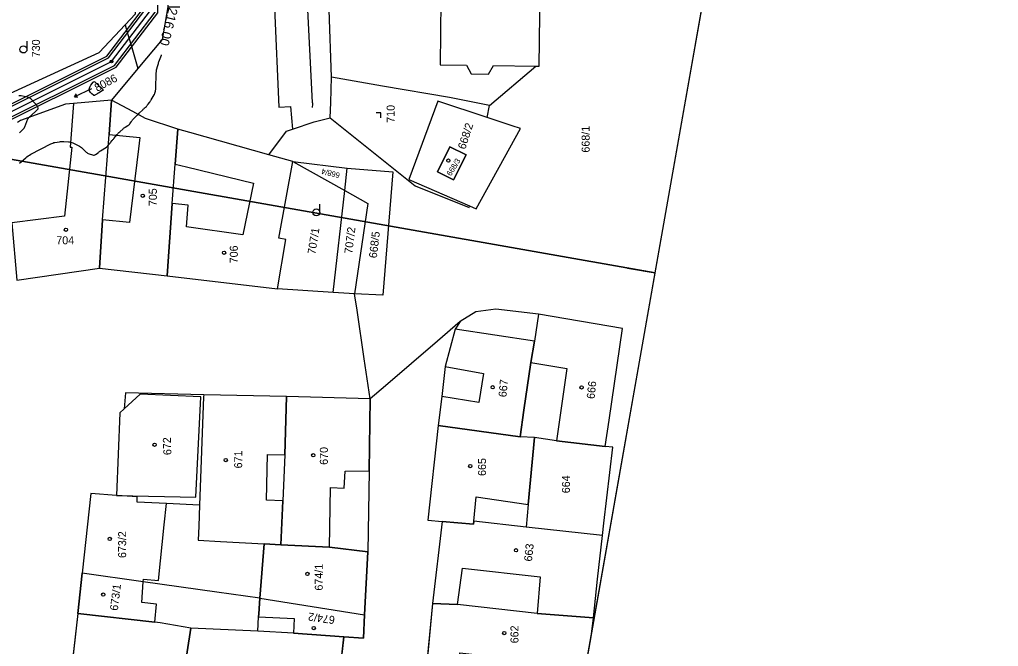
# Model space of a CAD drawing. Extents: x -534481 to -534256, y -1190577 to -1190138.
# Drawn here: x -534365.7 to -534261.7, y -1190410 to -1190343.4 of the extents above; entities that cross this region are included whole.
import ezdxf

# ---------------------------------------------------------------- set-up
doc = ezdxf.new("R2010")
doc.units = 0
for name, color, linetype in [('0_kroužky', 7, 'Continuous'), ('30', 7, 'Continuous'), ('31', 7, 'Continuous'), ('40', 7, 'Continuous'), ('_N_osa', 7, 'Continuous'), ('_N_tenká', 7, 'Continuous'), ('_rámeček', 7, 'Continuous'), ('_rámeček_mřížka', 7, 'Continuous'), ('Hranice parcel', 7, 'Continuous'), ('Parcelní čísla', 7, 'Continuous'), ('Polygon budovy', 7, 'Continuous'), ('Značky budov', 7, 'Continuous'), ('Značky kultur', 7, 'Continuous')]:
    doc.layers.add(name, color=color, linetype=linetype)

msp = doc.modelspace()

# ---------------------------------------------------------------- linework, layer by layer
at = {"layer": '0_kroužky'}
msp.add_circle((-534355.89, -1190347.82), 0.15, dxfattribs=at)
msp.add_circle((-534355.89, -1190347.82), 0.15, dxfattribs=at)
msp.add_circle((-534355.89, -1190347.82), 0.15, dxfattribs=at)
msp.add_circle((-534355.89, -1190347.82), 0.15, dxfattribs=at)
msp.add_circle((-534355.89, -1190347.82), 0.15, dxfattribs=at)
msp.add_circle((-534355.89, -1190347.82), 0.15, dxfattribs=at)
at = {"layer": '30'}
msp.add_lwpolyline([(-534365.67, -1190358.61), (-534365.01, -1190358.03), (-534364.89, -1190357.93), (-534364.76, -1190357.83), (-534364.62, -1190357.75), (-534364.48, -1190357.67), (-534362.35, -1190356.56), (-534362.24, -1190356.51), (-534362.13, -1190356.47), (-534362.02, -1190356.43), (-534361.9, -1190356.41), (-534361.42, -1190356.33), (-534361.3, -1190356.31), (-534361.18, -1190356.3), (-534361.07, -1190356.3), (-534360.95, -1190356.31), (-534360.47, -1190356.34), (-534360.35, -1190356.36), (-534360.23, -1190356.38), (-534360.12, -1190356.42), (-534360.01, -1190356.46), (-534359.42, -1190356.74), (-534359.31, -1190356.79), (-534359.2, -1190356.86), (-534359.1, -1190356.94), (-534359, -1190357.02), (-534358.59, -1190357.43), (-534358.52, -1190357.49), (-534358.44, -1190357.54), (-534358.36, -1190357.58), (-534358.28, -1190357.61), (-534357.9, -1190357.73), (-534357.82, -1190357.75), (-534357.75, -1190357.75), (-534357.68, -1190357.73), (-534357.6, -1190357.69), (-534357.33, -1190357.5), (-534357.26, -1190357.45), (-534357.19, -1190357.4), (-534357.12, -1190357.35), (-534357.05, -1190357.31), (-534356.43, -1190356.9), (-534356.39, -1190356.87), (-534356.35, -1190356.84), (-534356.31, -1190356.8), (-534356.27, -1190356.76), (-534356.14, -1190356.6), (-534356.1, -1190356.56), (-534356.07, -1190356.52), (-534356.04, -1190356.47), (-534356.01, -1190356.43), (-534355.83, -1190356.21), (-534355.78, -1190356.16), (-534355.74, -1190356.1), (-534355.7, -1190356.05), (-534355.66, -1190356), (-534355.31, -1190355.57), (-534355.24, -1190355.49), (-534355.17, -1190355.42), (-534355.1, -1190355.34), (-534355.02, -1190355.27), (-534354.67, -1190354.95), (-534354.62, -1190354.9), (-534354.56, -1190354.85), (-534354.49, -1190354.81), (-534354.43, -1190354.77), (-534354.15, -1190354.62), (-534354.09, -1190354.58), (-534354.04, -1190354.54), (-534354, -1190354.5), (-534353.96, -1190354.45), (-534353.82, -1190354.23), (-534353.78, -1190354.17), (-534353.74, -1190354.12), (-534353.7, -1190354.07), (-534353.65, -1190354.02), (-534353.28, -1190353.63), (-534353.2, -1190353.55), (-534353.12, -1190353.47), (-534353.04, -1190353.39), (-534352.96, -1190353.31), (-534352.57, -1190352.93), (-534352.52, -1190352.89), (-534352.47, -1190352.84), (-534352.43, -1190352.8), (-534352.38, -1190352.75), (-534352.19, -1190352.58), (-534352.15, -1190352.53), (-534352.11, -1190352.48), (-534352.06, -1190352.43), (-534352.02, -1190352.38), (-534351.83, -1190352.13), (-534351.79, -1190352.07), (-534351.75, -1190352), (-534351.71, -1190351.94), (-534351.67, -1190351.88), (-534351.37, -1190351.37), (-534351.34, -1190351.32), (-534351.32, -1190351.27), (-534351.3, -1190351.22), (-534351.29, -1190351.17), (-534351.23, -1190350.95), (-534351.22, -1190350.9), (-534351.21, -1190350.84), (-534351.2, -1190350.79), (-534351.2, -1190350.73), (-534351.19, -1190350.43), (-534351.19, -1190350.36), (-534351.19, -1190350.29), (-534351.19, -1190350.22), (-534351.18, -1190350.15), (-534351.15, -1190349.59), (-534351.15, -1190349.51), (-534351.15, -1190349.44), (-534351.15, -1190349.37), (-534351.14, -1190349.29), (-534351.14, -1190348.99), (-534351.13, -1190348.92), (-534351.12, -1190348.85), (-534351.11, -1190348.77), (-534351.1, -1190348.7), (-534350.98, -1190348.23), (-534350.95, -1190348.13), (-534350.92, -1190348.03), (-534350.89, -1190347.93), (-534350.85, -1190347.83), (-534350.6, -1190347.14), (-534350.59, -1190347.09)], dxfattribs=at)
at = {"layer": '31'}
for points in [[(-534334.53, -1190352.7), (-534334.5, -1190352.33), (-534334.5, -1190352.32), (-534334.5, -1190352.32), (-534334.5, -1190352.31), (-534334.5, -1190352.31), (-534334.5, -1190352.31), (-534334.5, -1190352.3), (-534334.5, -1190352.29), (-534334.52, -1190352.22), (-534334.52, -1190352.19), (-534334.53, -1190352.19), (-534334.53, -1190352.18), (-534334.53, -1190352.18), (-534334.53, -1190352.17), (-534335.72, -1190328.89)], [(-534365.67, -1190355.38), (-534365.51, -1190355.23), (-534365.47, -1190355.19), (-534365.43, -1190355.15), (-534365.4, -1190355.12), (-534365.36, -1190355.08), (-534365.22, -1190354.92), (-534365.18, -1190354.88), (-534365.15, -1190354.84), (-534365.13, -1190354.79), (-534365.1, -1190354.75), (-534364.77, -1190353.91), (-534364.76, -1190353.88), (-534364.75, -1190353.86), (-534364.73, -1190353.83), (-534364.71, -1190353.81), (-534364.63, -1190353.73), (-534364.61, -1190353.71), (-534364.59, -1190353.69), (-534364.57, -1190353.67), (-534364.55, -1190353.65), (-534363.75, -1190352.9), (-534363.74, -1190352.89), (-534363.74, -1190352.89), (-534363.72, -1190352.88), (-534363.71, -1190352.87), (-534363.71, -1190352.87), (-534363.69, -1190352.85), (-534363.69, -1190352.85), (-534363.68, -1190352.84), (-534363.68, -1190352.84), (-534363.68, -1190352.83), (-534363.68, -1190352.8), (-534363.68, -1190352.79), (-534363.68, -1190352.78), (-534363.68, -1190352.77), (-534363.68, -1190352.76), (-534363.73, -1190352.64), (-534363.74, -1190352.62), (-534363.75, -1190352.6), (-534363.76, -1190352.58), (-534363.77, -1190352.56), (-534364.35, -1190351.88), (-534364.45, -1190351.77), (-534364.57, -1190351.69), (-534364.7, -1190351.63), (-534364.84, -1190351.59), (-534365.49, -1190351.46), (-534365.61, -1190351.45), (-534365.73, -1190351.46)]]:
    msp.add_lwpolyline(points, dxfattribs=at)
msp.add_lwpolyline([(-534357.7, -1190351.42), (-534357.74, -1190351.42), (-534357.78, -1190351.41), (-534357.82, -1190351.38), (-534357.99, -1190351.24), (-534358.03, -1190351.2), (-534358.06, -1190351.17), (-534358.1, -1190351.13), (-534358.13, -1190351.09), (-534358.24, -1190350.93), (-534358.26, -1190350.88), (-534358.27, -1190350.84), (-534358.27, -1190350.8), (-534358.26, -1190350.75), (-534358.19, -1190350.53), (-534358.17, -1190350.48), (-534358.15, -1190350.43), (-534358.12, -1190350.39), (-534358.09, -1190350.34), (-534357.85, -1190350.02), (-534357.79, -1190349.97), (-534357.74, -1190349.95), (-534357.68, -1190349.96), (-534357.62, -1190350), (-534357.38, -1190350.24), (-534357.32, -1190350.3), (-534357.26, -1190350.36), (-534357.2, -1190350.42), (-534357.14, -1190350.48), (-534356.86, -1190350.72), (-534356.81, -1190350.78), (-534356.79, -1190350.84), (-534356.82, -1190350.89), (-534356.88, -1190350.94), (-534357.27, -1190351.16), (-534357.32, -1190351.19), (-534357.37, -1190351.22), (-534357.41, -1190351.25), (-534357.46, -1190351.28), (-534357.65, -1190351.4)], close=True, dxfattribs=at)
at = {"layer": '_N_osa'}
msp.add_lwpolyline([(-534409.87, -1190391.44), (-534405.95, -1190382.82), (-534400.87, -1190377.49), (-534393.7, -1190372.72), (-534384.93, -1190365.48), (-534382.63, -1190361.15), (-534355.89, -1190347.82), (-534351.74, -1190342.39), (-534351.58, -1190328.32), (-534347.2, -1190300.92), (-534345.55, -1190283.64), (-534344.68, -1190264.49)], dxfattribs=at)
at = {"layer": '_N_tenká'}
for points in [[(-534409.92, -1190390.34), (-534406.37, -1190382.53), (-534401.2, -1190377.1), (-534393.99, -1190372.32), (-534385.32, -1190365.15), (-534383, -1190360.77), (-534356.22, -1190347.43), (-534352.24, -1190342.22), (-534352.08, -1190328.27), (-534347.7, -1190300.86), (-534346.05, -1190283.61), (-534345.26, -1190266.1)], [(-534409.88, -1190389.65), (-534406.58, -1190382.39), (-534401.36, -1190376.91), (-534394.14, -1190372.11), (-534385.52, -1190364.99), (-534383.18, -1190360.58), (-534356.38, -1190347.23), (-534352.48, -1190342.13), (-534352.33, -1190328.25), (-534347.95, -1190300.83), (-534346.3, -1190283.59), (-534345.51, -1190266.12)], [(-534409.36, -1190391.54), (-534405.53, -1190383.1), (-534400.55, -1190377.87), (-534393.4, -1190373.12), (-534384.53, -1190365.8), (-534382.26, -1190361.52), (-534355.57, -1190348.22), (-534351.24, -1190342.56), (-534351.08, -1190328.36), (-534346.71, -1190300.98), (-534345.05, -1190283.68), (-534344.26, -1190266.14)], [(-534409.11, -1190391.59), (-534405.32, -1190383.24), (-534400.39, -1190378.07), (-534393.25, -1190373.32), (-534384.33, -1190365.96), (-534382.08, -1190361.71), (-534355.4, -1190348.42), (-534350.99, -1190342.65), (-534350.83, -1190328.38), (-534346.46, -1190301.02), (-534344.8, -1190283.69), (-534344.01, -1190266.2)]]:
    msp.add_lwpolyline(points, dxfattribs=at)
at = {"layer": '_rámeček'}
for p, q in [((-534298.13, -1190370.27), (-534279.9, -1190266.87)), ((-534316.37, -1190473.68), (-534298.13, -1190370.27))]:
    msp.add_line(p, q, dxfattribs=at)
for points in [[(-534407.91, -1190137.67), (-534480.84, -1190551.29), (-534334.6, -1190577.08), (-534261.67, -1190163.46)], [(-534333.07, -1190257.49), (-534426.15, -1190241.08), (-534444.38, -1190344.48), (-534298.13, -1190370.27)], [(-534298.13, -1190370.27), (-534444.38, -1190344.48), (-534462.61, -1190447.89), (-534316.37, -1190473.68)]]:
    msp.add_lwpolyline(points, dxfattribs=at)
at = {"layer": '_rámeček_mřížka'}
msp.add_line((-534301.09, -1190369.75), (-534298.13, -1190370.27), dxfattribs=at)
msp.add_lwpolyline([(-534480.84, -1190551.29), (-534334.6, -1190577.08), (-534261.67, -1190163.46)], dxfattribs=at)
at = {"layer": 'Hranice parcel'}
for p, q in [((-534353.09, -1190348.56), (-534355.88, -1190351.91)), ((-534315.98, -1190353.76), (-534315.73, -1190352.48)), ((-534336.63, -1190358.42), (-534339.19, -1190357.71)), ((-534336.63, -1190358.42), (-534330.85, -1190359.15)), ((-534336.63, -1190358.42), (-534331.12, -1190361.52)), ((-534331.12, -1190361.52), (-534330.85, -1190359.15)), ((-534332.34, -1190372.35), (-534331.12, -1190361.52)), ((-534365.97, -1190371.05), (-534357.17, -1190369.75)), ((-534357.17, -1190369.75), (-534349.98, -1190370.59)), ((-534349.98, -1190370.59), (-534338.27, -1190371.97)), ((-534332.34, -1190372.35), (-534338.27, -1190371.97)), ((-534330.07, -1190372.49), (-534332.34, -1190372.35)), ((-534310.54, -1190374.65), (-534315.06, -1190374.11)), ((-534310.54, -1190374.65), (-534310.94, -1190377.52)), ((-534301.59, -1190376.19), (-534310.54, -1190374.65)), ((-534337.31, -1190383.4), (-534346.1, -1190383.23)), ((-534328.4, -1190383.66), (-534337.31, -1190383.4)), ((-534312.48, -1190387.67), (-534321.18, -1190386.48)), ((-534310.97, -1190387.76), (-534312.48, -1190387.67)), ((-534310.97, -1190387.76), (-534311.63, -1190394.88)), ((-534358.08, -1190393.72), (-534359.01, -1190402.18)), ((-534355.36, -1190393.91), (-534358.08, -1190393.72)), ((-534311.63, -1190394.88), (-534311.85, -1190397.27)), ((-534320.78, -1190396.67), (-534321.81, -1190405.38)), ((-534303.73, -1190398.17), (-534311.85, -1190397.27)), ((-534340.13, -1190404.83), (-534339.69, -1190399.07)), ((-534339.69, -1190399.07), (-534337.9, -1190399.17)), ((-534328.66, -1190399.89), (-534329, -1190406.6)), ((-534359.48, -1190406.45), (-534359.01, -1190402.18)), ((-534340.26, -1190406.48), (-534340.13, -1190404.83)), ((-534340.13, -1190404.83), (-534329, -1190406.6)), ((-534321.81, -1190405.38), (-534322.86, -1190416.77)), ((-534359.48, -1190406.45), (-534361.32, -1190422.75)), ((-534340.34, -1190408.33), (-534347.45, -1190408.02)), ((-534331.23, -1190408.93), (-534332.91, -1190424.36))]:
    msp.add_line(p, q, dxfattribs=at)
for points in [[(-534354.46, -1190343.91), (-534353.36, -1190342.74), (-534353.4, -1190337.34)], [(-534349.69, -1190337.24), (-534349.69, -1190337.44), (-534349.9, -1190342.02), (-534350.53, -1190345.48), (-534353.09, -1190348.56)], [(-534332.53, -1190349.48), (-534332.78, -1190342.31), (-534332.83, -1190337.12)], [(-534315.73, -1190352.48), (-534310.81, -1190348.3), (-534310.45, -1190348.3), (-534310.32, -1190337.38), (-534310.32, -1190337.25)], [(-534374.45, -1190354.76), (-534357.22, -1190346.86), (-534354.46, -1190343.91)], [(-534354.46, -1190343.91), (-534354.18, -1190344.85), (-534353.82, -1190346.09), (-534353.09, -1190348.56)], [(-534332.65, -1190353.81), (-534332.6, -1190352.16), (-534332.53, -1190349.48)], [(-534315.73, -1190352.48), (-534320, -1190351.64), (-534327.1, -1190350.42), (-534332.53, -1190349.48)], [(-534355.88, -1190351.91), (-534359.93, -1190352.28), (-534360.78, -1190352.36), (-534365.58, -1190354.08), (-534365.87, -1190354.29)], [(-534357.17, -1190369.75), (-534356.84, -1190364.64), (-534356.15, -1190355.55), (-534355.88, -1190351.91)], [(-534348.86, -1190355), (-534352.29, -1190353.85), (-534353.64, -1190353.12), (-534355.88, -1190351.91)], [(-534315.98, -1190353.76), (-534321.21, -1190352.03), (-534324.29, -1190360.33), (-534317.85, -1190363.15)], [(-534339.19, -1190357.71), (-534337.29, -1190355.2), (-534336.67, -1190354.99), (-534334.35, -1190354.21), (-534332.65, -1190353.81)], [(-534332.65, -1190353.81), (-534323.62, -1190361.03), (-534317.88, -1190363.31), (-534317.85, -1190363.15)], [(-534317.85, -1190363.15), (-534317.16, -1190363.45), (-534312.43, -1190354.94), (-534313.32, -1190354.65), (-534315.98, -1190353.76)], [(-534349.98, -1190370.59), (-534349.44, -1190362.88), (-534349.13, -1190358.72), (-534348.86, -1190355)], [(-534339.19, -1190357.71), (-534347.58, -1190355.36), (-534348.86, -1190355)], [(-534318.22, -1190357.73), (-534319.55, -1190360.4), (-534321.26, -1190359.54), (-534319.94, -1190356.87), (-534318.22, -1190357.73)], [(-534338.27, -1190371.97), (-534337.38, -1190366.71), (-534338.11, -1190366.57), (-534336.63, -1190358.42)], [(-534330.85, -1190359.15), (-534326, -1190359.52), (-534327.08, -1190372.63), (-534330.07, -1190372.49)], [(-534331.12, -1190361.52), (-534328.67, -1190362.89), (-534330.07, -1190372.49)], [(-534328.4, -1190383.66), (-534329.04, -1190379.4), (-534329.81, -1190374.24), (-534330.07, -1190372.49)], [(-534315.06, -1190374.11), (-534317.18, -1190374.42), (-534318.86, -1190375.44)], [(-534318.86, -1190375.44), (-534321.27, -1190377.51), (-534326.78, -1190382.26), (-534328.4, -1190383.66)], [(-534318.86, -1190375.44), (-534319.37, -1190376.25), (-534320.44, -1190380.21), (-534320.81, -1190383.39), (-534321.18, -1190386.48)], [(-534303.44, -1190388.7), (-534303.03, -1190385.92), (-534301.59, -1190376.19)], [(-534310.94, -1190377.52), (-534311.35, -1190379.79), (-534312.08, -1190384.85), (-534312.48, -1190387.67)], [(-534346.1, -1190383.23), (-534354.41, -1190383.01), (-534354.55, -1190384.72), (-534355, -1190385.14), (-534355.36, -1190393.91)], [(-534346.1, -1190383.23), (-534346.11, -1190383.45), (-534346.53, -1190394.95)], [(-534337.31, -1190383.4), (-534337.47, -1190389.59), (-534337.69, -1190394.47), (-534337.9, -1190399.17)], [(-534328.4, -1190383.66), (-534328.51, -1190391.31), (-534328.66, -1190399.89)], [(-534321.18, -1190386.48), (-534322.3, -1190396.55), (-534320.78, -1190396.67)], [(-534303.44, -1190388.7), (-534308.63, -1190388.11), (-534310.97, -1190387.76)], [(-534303.73, -1190398.17), (-534303.58, -1190396.85), (-534302.64, -1190388.78), (-534303.44, -1190388.7)], [(-534346.53, -1190394.95), (-534350.05, -1190394.78), (-534353.16, -1190394.63), (-534353.18, -1190394.06), (-534355.29, -1190393.91), (-534355.36, -1190393.91)], [(-534346.53, -1190394.95), (-534346.62, -1190397.16), (-534346.69, -1190398.67), (-534344.32, -1190398.81), (-534339.69, -1190399.07)], [(-534311.85, -1190397.27), (-534317.4, -1190396.66), (-534317.42, -1190396.96), (-534320.78, -1190396.67)], [(-534304.7, -1190406.9), (-534304.25, -1190402.82), (-534303.73, -1190398.17)], [(-534337.9, -1190399.17), (-534332.75, -1190399.41), (-534328.66, -1190399.89)], [(-534340.13, -1190404.83), (-534344.71, -1190404.18), (-534352.53, -1190403.09), (-534359.01, -1190402.18)], [(-534304.7, -1190406.9), (-534310.69, -1190406.47), (-534319.12, -1190405.49), (-534321.81, -1190405.38)], [(-534347.45, -1190408.02), (-534350.73, -1190407.46), (-534351.28, -1190407.37), (-534359.48, -1190406.45)], [(-534340.34, -1190408.33), (-534340.27, -1190406.79), (-534340.26, -1190406.48)], [(-534329, -1190406.6), (-534329.13, -1190409.08), (-534331.23, -1190408.93)], [(-534304.95, -1190408.92), (-534304.7, -1190406.9)], [(-534347.45, -1190408.02), (-534348.24, -1190413.03), (-534349.11, -1190420.99), (-534349.31, -1190422.85)], [(-534331.23, -1190408.93), (-534336.56, -1190408.56), (-534340.34, -1190408.33)]]:
    msp.add_lwpolyline(points, dxfattribs=at)
at = {"layer": 'Polygon budovy'}
msp.add_line((-534306.7, -1190418.82), (-534304.95, -1190408.92), dxfattribs=at)
for points in [[(-534349.9, -1190342.02), (-534347.72, -1190341.99), (-534347.71, -1190342.39), (-534338.59, -1190342.1), (-534338.12, -1190352.66), (-534336.88, -1190352.6), (-534336.67, -1190354.99), (-534334.35, -1190354.21), (-534332.65, -1190353.81), (-534332.6, -1190352.16), (-534332.53, -1190349.48), (-534332.78, -1190342.31), (-534332.83, -1190337.12), (-534337.65, -1190337.15), (-534347.69, -1190337.23), (-534349.69, -1190337.24), (-534349.69, -1190337.44)], [(-534320.89, -1190337.07), (-534320.88, -1190337.18), (-534325.2, -1190337.17), (-534325.09, -1190341.34), (-534320.9, -1190341.35), (-534320.99, -1190348.17), (-534318.18, -1190348.21), (-534317.67, -1190349.12), (-534315.85, -1190349.15), (-534315.3, -1190348.25), (-534310.81, -1190348.3), (-534310.45, -1190348.3), (-534310.32, -1190337.38)], [(-534366.5, -1190364.95), (-534365.97, -1190371.05), (-534357.17, -1190369.75), (-534356.84, -1190364.64), (-534356.15, -1190355.55), (-534355.88, -1190351.91), (-534359.93, -1190352.28), (-534360.28, -1190356.91), (-534360.12, -1190356.93), (-534360.9, -1190364.23)], [(-534352.29, -1190353.85), (-534353.64, -1190353.12), (-534355.88, -1190351.91), (-534356.15, -1190355.55), (-534352.88, -1190355.89), (-534353.03, -1190357.09), (-534353.98, -1190364.91), (-534356.84, -1190364.64), (-534357.17, -1190369.75), (-534349.98, -1190370.59), (-534349.44, -1190362.88), (-534349.13, -1190358.72), (-534348.86, -1190355)], [(-534349.44, -1190362.88), (-534349.98, -1190370.59), (-534338.27, -1190371.97), (-534337.38, -1190366.71), (-534338.11, -1190366.57), (-534336.63, -1190358.42), (-534339.19, -1190357.71), (-534347.58, -1190355.36), (-534348.86, -1190355), (-534349.13, -1190358.72), (-534347.93, -1190359.01), (-534340.81, -1190360.75), (-534341.96, -1190366.24), (-534347.94, -1190365.39), (-534347.74, -1190363.06)], [(-534321.26, -1190359.54), (-534319.55, -1190360.4), (-534318.22, -1190357.73), (-534319.94, -1190356.87)], [(-534311.35, -1190379.79), (-534307.52, -1190380.43), (-534308.63, -1190388.11), (-534303.44, -1190388.7), (-534303.03, -1190385.92), (-534301.59, -1190376.19), (-534310.54, -1190374.65), (-534310.94, -1190377.52)], [(-534316.87, -1190384.03), (-534320.81, -1190383.39), (-534321.18, -1190386.48), (-534312.48, -1190387.67), (-534312.08, -1190384.85), (-534311.35, -1190379.79), (-534310.94, -1190377.52), (-534319.37, -1190376.25), (-534320.44, -1190380.21), (-534316.39, -1190380.95)], [(-534355.36, -1190393.91), (-534355.29, -1190393.91), (-534346.92, -1190394.09), (-534346.41, -1190383.44), (-534352.85, -1190383.16), (-534354.55, -1190384.72), (-534355, -1190385.14)], [(-534344.32, -1190398.81), (-534339.69, -1190399.07), (-534337.9, -1190399.17), (-534337.69, -1190394.47), (-534339.43, -1190394.43), (-534339.31, -1190389.56), (-534337.47, -1190389.59), (-534337.31, -1190383.4), (-534346.1, -1190383.23), (-534346.11, -1190383.45), (-534346.53, -1190394.95), (-534346.62, -1190397.16), (-534346.69, -1190398.67)], [(-534332.62, -1190393.06), (-534331.17, -1190393.14), (-534331.06, -1190391.32), (-534328.51, -1190391.31), (-534328.4, -1190383.66), (-534337.31, -1190383.4), (-534337.47, -1190389.59), (-534337.69, -1190394.47), (-534337.9, -1190399.17), (-534332.75, -1190399.41)], [(-534322.3, -1190396.55), (-534320.78, -1190396.67), (-534317.42, -1190396.96), (-534317.4, -1190396.66), (-534317.14, -1190394.07), (-534311.63, -1190394.88), (-534310.97, -1190387.76), (-534312.48, -1190387.67), (-534321.18, -1190386.48)], [(-534359.48, -1190406.45), (-534351.28, -1190407.37), (-534351.13, -1190405.45), (-534352.67, -1190405.29), (-534352.53, -1190403.09), (-534352.51, -1190402.82), (-534350.91, -1190402.96), (-534350.29, -1190397.04), (-534350.05, -1190394.78), (-534353.16, -1190394.63), (-534353.18, -1190394.06), (-534355.29, -1190393.91), (-534355.36, -1190393.91), (-534358.08, -1190393.72), (-534359.01, -1190402.18)], [(-534317.4, -1190396.66), (-534317.42, -1190396.96), (-534320.78, -1190396.67), (-534321.81, -1190405.38), (-534319.12, -1190405.49), (-534318.59, -1190401.64), (-534310.36, -1190402.55), (-534310.69, -1190406.47), (-534304.7, -1190406.9), (-534304.25, -1190402.82), (-534303.73, -1190398.17), (-534311.85, -1190397.27)], [(-534329, -1190406.6), (-534328.66, -1190399.89), (-534332.75, -1190399.41), (-534337.9, -1190399.17), (-534339.69, -1190399.07), (-534340.13, -1190404.83), (-534340.26, -1190406.48), (-534340.27, -1190406.79), (-534336.48, -1190406.99), (-534336.56, -1190408.56), (-534331.23, -1190408.93), (-534329.13, -1190409.08)], [(-534350.73, -1190407.46), (-534351.28, -1190407.37), (-534359.48, -1190406.45), (-534361.32, -1190422.75), (-534349.49, -1190424.31), (-534349.31, -1190422.85), (-534349.11, -1190420.99), (-534351.71, -1190420.68), (-534353.09, -1190421.73), (-534356.12, -1190421.36), (-534355.1, -1190412.3), (-534348.24, -1190413.03), (-534347.45, -1190408.02)], [(-534349.31, -1190422.85), (-534346.43, -1190423.17), (-534346.07, -1190420.03), (-534344.47, -1190420.16), (-534344.27, -1190417.73), (-534345.78, -1190417.61), (-534345.25, -1190412.99), (-534338.47, -1190413.36), (-534338.99, -1190419.24), (-534337.36, -1190419.45), (-534337.91, -1190424.11), (-534332.91, -1190424.36), (-534331.23, -1190408.93), (-534336.56, -1190408.56), (-534340.34, -1190408.33), (-534347.45, -1190408.02), (-534348.24, -1190413.03), (-534349.11, -1190420.99)]]:
    msp.add_lwpolyline(points, close=True, dxfattribs=at)
msp.add_lwpolyline([(-534304.95, -1190408.92), (-534304.7, -1190406.9), (-534310.69, -1190406.47), (-534319.12, -1190405.49), (-534321.81, -1190405.38), (-534322.86, -1190416.77), (-534319.66, -1190417.17), (-534318.89, -1190410.64), (-534311.23, -1190411.47), (-534311.53, -1190414.36), (-534313.6, -1190414.13), (-534314.01, -1190417.87), (-534306.7, -1190418.82)], dxfattribs=at)
at = {"layer": 'Značky budov'}
for centre in [(-534320.11, -1190358.34), (-534352.58, -1190362.07), (-534360.74, -1190365.68), (-534343.93, -1190368.13), (-534315.4, -1190382.41), (-534305.95, -1190382.44), (-534351.32, -1190388.52), (-534334.46, -1190389.64), (-534343.75, -1190390.16), (-534317.78, -1190390.8), (-534356.08, -1190398.53), (-534312.92, -1190399.73), (-534335.08, -1190402.25), (-534356.77, -1190404.44), (-534334.41, -1190408.01), (-534314.17, -1190408.54)]:
    msp.add_circle(centre, 0.175, dxfattribs=at)
at = {"layer": 'Značky kultur'}
for p, q in [((-534364.87, -1190346.53), (-534364.87, -1190345.66)), ((-534358.01, -1190350.7), (-534359.83, -1190351.55)), ((-534359.83, -1190351.55), (-534359.6, -1190351.26)), ((-534359.83, -1190351.55), (-534359.46, -1190351.56)), ((-534327.29, -1190353.28), (-534327.79, -1190353.28)), ((-534327.29, -1190353.78), (-534327.29, -1190353.28)), ((-534333.75, -1190363.84), (-534333.75, -1190362.96))]:
    msp.add_line(p, q, dxfattribs=at)
for centre in [(-534365.25, -1190346.53), (-534334.13, -1190363.84)]:
    msp.add_circle(centre, 0.375, dxfattribs=at)

# ---------------------------------------------------------------- texts
at = {"layer": '40'}
msp.add_text('216.00', height=1, rotation=255.7671, dxfattribs=at).set_placement((-534349.81, -1190342.02))
at = {"layer": 'Parcelní čísla'}
for s, height, rotation, p in [('730', 0.85, 90, (-534363.5, -1190347.36)), ('8086', 0.85, 27.9902, (-534357.42, -1190351.04)), ('710', 0.85, 90, (-534325.81, -1190354.32)), ('668/2', 0.85, 72, (-534318.32, -1190357.21)), ('668/1', 0.85, 90, (-534305.1, -1190357.49)), ('668/3', 0.595, 58, (-534319.84, -1190360.03)), ('668/4', 0.595, 166.3082, (-534331.58, -1190359.64)), ('705', 0.85, 90, (-534351.08, -1190363.18)), ('707/1', 0.85, 81, (-534334.24, -1190368.35)), ('707/2', 0.85, 83, (-534330.32, -1190368.27)), ('668/5', 0.85, 83, (-534327.72, -1190368.74)), ('706', 0.85, 90, (-534342.48, -1190369.25)), ('667', 0.85, 85, (-534313.94, -1190383.5)), ('666', 0.85, 84, (-534304.58, -1190383.69)), ('672', 0.85, 92, (-534349.53, -1190389.61)), ('671', 0.85, 90, (-534342.01, -1190391.04)), ('670', 0.85, 90, (-534332.91, -1190390.66)), ('665', 0.85, 90, (-534316.11, -1190391.84)), ('664', 0.85, 90, (-534307.19, -1190393.68)), ('673/2', 0.85, 90, (-534354.34, -1190400.56)), ('663', 0.85, 84, (-534311.23, -1190400.96)), ('674/1', 0.85, 90, (-534333.45, -1190404.02)), ('673/1', 0.85, 83, (-534355.23, -1190406.19)), ('674/2', 0.85, 172, (-534332.12, -1190406.75)), ('662', 0.85, 90, (-534312.66, -1190409.62))]:
    msp.add_text(s, height=height, rotation=rotation, dxfattribs=at).set_placement(p)
msp.add_text('704', height=0.85, dxfattribs=at).set_placement((-534361.76, -1190367.23))

doc.saveas('drawing.dxf')
